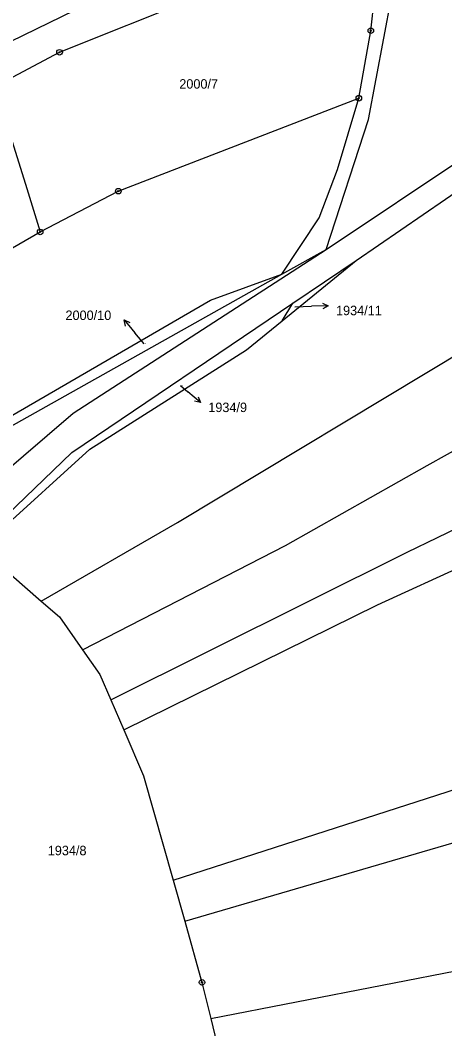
# Model space of a CAD drawing. Extents: x -763205 to -760228, y -1155311 to -1152844.
# Drawn here: x -761573.8 to -761497.6, y -1154597.9 to -1154416.7 of the extents above; entities that cross this region are included whole.
import ezdxf

# ---------------------------------------------------------------- set-up
doc = ezdxf.new("R2010")
doc.units = 0
for name, color, linetype in [('Vrstva 1', 7, 'Continuous'), ('Vrstva 16', 7, 'Continuous'), ('Vrstva 18', 7, 'Continuous'), ('Vrstva 24', 7, 'Continuous'), ('Vrstva 6', 7, 'Continuous')]:
    doc.layers.add(name, color=color, linetype=linetype)

msp = doc.modelspace()

# ---------------------------------------------------------------- linework, layer by layer
at = {"layer": 'Vrstva 1'}
for p, q in [((-761566.76, -1154422.44), (-761508.72, -1154399.14)), ((-761518.92, -1154457.86), (-761438.39, -1154403.96)), ((-761510.87, -1154418.57), (-761509.65, -1154407.59)), ((-761513.5, -1154459.86), (-761451.03, -1154416.74)), ((-761513.04, -1154430.7), (-761510.87, -1154418.57)), ((-761578.33, -1154428.54), (-761566.76, -1154422.44)), ((-761556.22, -1154447.39), (-761513.04, -1154430.7)), ((-761575.61, -1154437.36), (-761572.9, -1154446.15)), ((-761572.9, -1154446.15), (-761570.25, -1154454.72)), ((-761570.25, -1154454.72), (-761556.22, -1154447.39)), ((-761564.32, -1154487.26), (-761518.92, -1154457.86)), ((-761526.87, -1154462.32), (-761518.92, -1154457.86)), ((-761524.86, -1154467.53), (-761513.5, -1154459.86)), ((-761602.35, -1154504.66), (-761526.87, -1154462.32)), ((-761564.56, -1154494.35), (-761524.86, -1154467.53)), ((-761586.13, -1154505.98), (-761564.32, -1154487.26)), ((-761581.7, -1154510.84), (-761564.56, -1154494.35))]:
    msp.add_line(p, q, dxfattribs=at)
at = {"layer": 'Vrstva 16'}
for p, q in [((-761524.5, -1154468.17), (-761521.52, -1154468.08)), ((-761518.521, -1154467.985), (-761521.52, -1154468.08)), ((-761555.173, -1154470.538), (-761553.25, -1154472.84)), ((-761551.58, -1154474.84), (-761553.25, -1154472.84)), ((-761545.03, -1154482.31), (-761543.73, -1154483.43)), ((-761541.452, -1154485.382), (-761543.73, -1154483.43))]:
    msp.add_line(p, q, dxfattribs=at)
for points in [[(-761519.537, -1154467.517), (-761518.521, -1154467.985), (-761519.505, -1154468.517)], [(-761554.916, -1154471.626), (-761555.173, -1154470.538), (-761554.149, -1154470.985)], [(-761541.886, -1154484.352), (-761541.452, -1154485.382), (-761542.536, -1154485.111)]]:
    msp.add_lwpolyline(points, dxfattribs=at)
at = {"layer": 'Vrstva 24'}
for centre, radius in [((-761510.87, -1154418.57), 0.5), ((-761510.87, -1154418.57), 0.1), ((-761566.76, -1154422.44), 0.5), ((-761566.76, -1154422.44), 0.1), ((-761513.04, -1154430.7), 0.5), ((-761513.04, -1154430.7), 0.1), ((-761556.22, -1154447.39), 0.5), ((-761556.22, -1154447.39), 0.1), ((-761570.25, -1154454.72), 0.5), ((-761570.25, -1154454.72), 0.1), ((-761541.19, -1154589.52), 0.5), ((-761541.19, -1154589.52), 0.1)]:
    msp.add_circle(centre, radius, dxfattribs=at)
at = {"layer": 'Vrstva 6'}
for p, q in [((-761606.34, -1154435.54), (-761546.43, -1154406.25)), ((-761511.31, -1154434.52), (-761505.97, -1154406.33)), ((-761516.89, -1154443.51), (-761513.04, -1154430.7)), ((-761518.92, -1154457.86), (-761511.31, -1154434.52)), ((-761520.18, -1154452.21), (-761516.89, -1154443.51)), ((-761526.87, -1154462.32), (-761520.18, -1154452.21)), ((-761608.96, -1154477.08), (-761570.25, -1154454.72)), ((-761526.8, -1154470.69), (-761513.5, -1154459.86)), ((-761545.6, -1154506.91), (-761468.46, -1154460.44)), ((-761539.68, -1154466.97), (-761526.87, -1154462.32)), ((-761594.03, -1154498.55), (-761539.68, -1154466.97)), ((-761526.8, -1154470.69), (-761524.86, -1154467.53)), ((-761533.22, -1154475.92), (-761526.8, -1154470.69)), ((-761509.67, -1154521.7), (-761401.81, -1154472.06)), ((-761561.35, -1154493.76), (-761533.22, -1154475.92)), ((-761504.37, -1154512.25), (-761428.7, -1154475.47)), ((-761500.76, -1154496.7), (-761467.32, -1154477.9)), ((-761578.38, -1154509.22), (-761561.35, -1154493.76)), ((-761526.22, -1154511.06), (-761500.76, -1154496.7)), ((-761570.06, -1154521.02), (-761545.6, -1154506.91)), ((-761581.7, -1154510.84), (-761570.06, -1154521.02)), ((-761562.65, -1154529.77), (-761526.22, -1154511.06)), ((-761557.55, -1154538.78), (-761504.37, -1154512.25)), ((-761570.06, -1154521.02), (-761566.78, -1154523.89)), ((-761555.24, -1154544.15), (-761509.67, -1154521.7)), ((-761566.78, -1154523.89), (-761562.65, -1154529.77)), ((-761562.65, -1154529.77), (-761559.53, -1154534.2)), ((-761559.53, -1154534.2), (-761557.55, -1154538.78)), ((-761557.55, -1154538.78), (-761555.24, -1154544.15)), ((-761555.24, -1154544.15), (-761551.68, -1154552.41)), ((-761546.38, -1154571.16), (-761463.44, -1154544.37)), ((-761551.68, -1154552.41), (-761546.38, -1154571.16)), ((-761544.3, -1154578.52), (-761483.91, -1154560.87)), ((-761546.38, -1154571.16), (-761544.3, -1154578.52)), ((-761544.3, -1154578.52), (-761541.19, -1154589.52)), ((-761539.61, -1154596.02), (-761484.45, -1154585.29)), ((-761541.19, -1154589.52), (-761539.61, -1154596.02)), ((-761539.61, -1154596.02), (-761534.9, -1154615.4))]:
    msp.add_line(p, q, dxfattribs=at)

# ---------------------------------------------------------------- texts
at = {"layer": 'Vrstva 16'}
for s, p in [('2000/10', (-761565.697, -1154470.54)), ('1934/11', (-761517.127, -1154469.68)), ('1934/9', (-761540.057, -1154487.08))]:
    msp.add_text(s, height=1.7, dxfattribs=at).set_placement(p)
at = {"layer": 'Vrstva 18'}
for s, height, p in [('2000/7', 1.7, (-761545.263, -1154428.98)), ('1934/11', 0.1, (-761524.477, -1154468.17)), ('2000/10', 0.1, (-761551.566, -1154474.84)), ('1934/9', 0.1, (-761545.007, -1154482.31)), ('1934/8', 1.7, (-761568.877, -1154566.69))]:
    msp.add_text(s, height=height, dxfattribs=at).set_placement(p)

doc.saveas('drawing.dxf')
